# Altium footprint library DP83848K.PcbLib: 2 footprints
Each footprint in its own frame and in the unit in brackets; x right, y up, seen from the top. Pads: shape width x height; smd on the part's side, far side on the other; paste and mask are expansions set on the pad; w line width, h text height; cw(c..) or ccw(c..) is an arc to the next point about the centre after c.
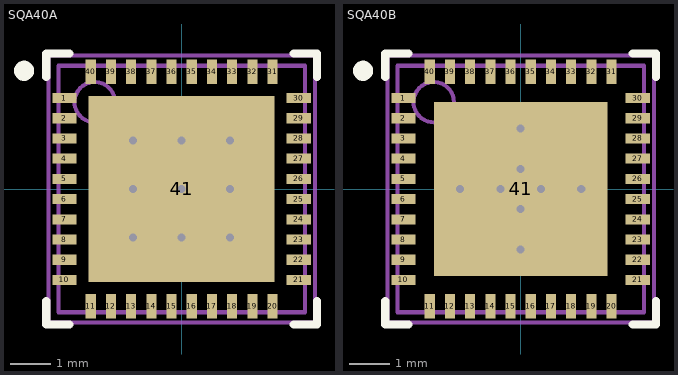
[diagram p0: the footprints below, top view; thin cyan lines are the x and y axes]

## SQA40A [mm] "QFN, 40-Leads, Body 6x6mm, Pitch 0.5mm, NSC Recommended"
height 0.8
pads (41):
  rect 0.6x0.25 smd paste-0.125 mask+0.051: 1(-2.9,2.25) 2(-2.9,1.75) 3(-2.9,1.25) 4(-2.9,0.75) 5(-2.9,0.25) 6(-2.9,-0.25) 7(-2.9,-0.75) 8(-2.9,-1.25) 9(-2.9,-1.75) 10(-2.9,-2.25) 21(2.9,-2.25) 22(2.9,-1.75) 23(2.9,-1.25) 24(2.9,-0.75) 25(2.9,-0.25) 26(2.9,0.25) 27(2.9,0.75) 28(2.9,1.25) 29(2.9,1.75) 30(2.9,2.25)
  rect 0.25x0.6 smd paste-0.125 mask+0.051: 11(-2.25,-2.9) 12(-1.75,-2.9) 13(-1.25,-2.9) 14(-0.75,-2.9) 15(-0.25,-2.9) 16(0.25,-2.9) 17(0.75,-2.9) 18(1.25,-2.9) 19(1.75,-2.9) 20(2.25,-2.9) 31(2.25,2.9) 32(1.75,2.9) 33(1.25,2.9) 34(0.75,2.9) 35(0.25,2.9) 36(-0.25,2.9) 37(-0.75,2.9) 38(-1.25,2.9) 39(-1.75,2.9) 40(-2.25,2.9)
  rect 4.6x4.6 smd paste-2.3 mask+0.051: 41(0,0)
via 1.2,0 diameter 0.5 hole 0.2
via -1.2,0 diameter 0.5 hole 0.2
via 0,0 diameter 0.5 hole 0.2
via 0,-1.2 diameter 0.5 hole 0.2
via -1.2,-1.2 diameter 0.5 hole 0.2
via 1.2,-1.2 diameter 0.5 hole 0.2
via 0,1.2 diameter 0.5 hole 0.2
via -1.2,1.2 diameter 0.5 hole 0.2
via 1.2,1.2 diameter 0.5 hole 0.2
Top Overlay:
  circle w0.25: c-3.9,2.925 r0.125
  lines w0.2: -3.35,-2.775 -3.35,-3.35 -2.775,-3.35 ; -3.35,2.775 -3.35,3.35 -2.775,3.35 ; 2.775,-3.35 3.35,-3.35 3.35,-2.775 ; 2.775,3.35 3.35,3.35 3.35,2.775
Top Paste:
  rectangle: 0.1,0.1 1.1,1.1
  rectangle: 1.3,1.3 2.3,2.3
  rectangle: 1.3,0.1 2.3,1.1
  rectangle: 0.1,1.3 1.1,2.3
  region: -0.1,2.3 -1.1,2.3 -1.1,1.3 -0.1,1.3
  region: -1.3,1.1 -2.3,1.1 -2.3,0.1 -1.3,0.1
  region: -1.3,2.3 -2.3,2.3 -2.3,1.3 -1.3,1.3
  region: -0.1,1.1 -1.1,1.1 -1.1,0.1 -0.1,0.1
  region: -0.1,-1.3 -1.1,-1.3 -1.1,-2.3 -0.1,-2.3
  region: -1.3,-0.1 -2.3,-0.1 -2.3,-1.1 -1.3,-1.1
  region: -1.3,-1.3 -2.3,-1.3 -2.3,-2.3 -1.3,-2.3
  region: -0.1,-0.1 -1.1,-0.1 -1.1,-1.1 -0.1,-1.1
  rectangle: 0.1,-2.3 1.1,-1.3
  rectangle: 1.3,-1.1 2.3,-0.1
  rectangle: 1.3,-2.3 2.3,-1.3
  rectangle: 0.1,-1.1 1.1,-0.1
  rectangle: -3.4,2.125 -2.7,2.375
  rectangle: -3.4,1.625 -2.7,1.875
  rectangle: -3.4,1.125 -2.7,1.375
  rectangle: -3.4,0.625 -2.7,0.875
  rectangle: -3.4,0.125 -2.7,0.375
  rectangle: -3.4,-0.375 -2.7,-0.125
  rectangle: -3.4,-0.875 -2.7,-0.625
  rectangle: -3.4,-1.375 -2.7,-1.125
  rectangle: -3.4,-1.875 -2.7,-1.625
  rectangle: -3.4,-2.375 -2.7,-2.125
  region: 2.375,-3.4 2.375,-2.7 2.125,-2.7 2.125,-3.4
  region: 1.875,-3.4 1.875,-2.7 1.625,-2.7 1.625,-3.4
  region: 1.375,-3.4 1.375,-2.7 1.125,-2.7 1.125,-3.4
  region: 0.875,-3.4 0.875,-2.7 0.625,-2.7 0.625,-3.4
  region: 0.375,-3.4 0.375,-2.7 0.125,-2.7 0.125,-3.4
  region: -0.125,-3.4 -0.125,-2.7 -0.375,-2.7 -0.375,-3.4
  region: -0.625,-3.4 -0.625,-2.7 -0.875,-2.7 -0.875,-3.4
  region: -1.125,-3.4 -1.125,-2.7 -1.375,-2.7 -1.375,-3.4
  region: -1.625,-3.4 -1.625,-2.7 -1.875,-2.7 -1.875,-3.4
  region: -2.125,-3.4 -2.125,-2.7 -2.375,-2.7 -2.375,-3.4
  region: 3.4,2.375 2.7,2.375 2.7,2.125 3.4,2.125
  region: 3.4,1.875 2.7,1.875 2.7,1.625 3.4,1.625
  region: 3.4,1.375 2.7,1.375 2.7,1.125 3.4,1.125
  region: 3.4,0.875 2.7,0.875 2.7,0.625 3.4,0.625
  region: 3.4,0.375 2.7,0.375 2.7,0.125 3.4,0.125
  region: 3.4,-0.125 2.7,-0.125 2.7,-0.375 3.4,-0.375
  region: 3.4,-0.625 2.7,-0.625 2.7,-0.875 3.4,-0.875
  region: 3.4,-1.125 2.7,-1.125 2.7,-1.375 3.4,-1.375
  region: 3.4,-1.625 2.7,-1.625 2.7,-1.875 3.4,-1.875
  region: 3.4,-2.125 2.7,-2.125 2.7,-2.375 3.4,-2.375
  region: -2.375,3.4 -2.375,2.7 -2.125,2.7 -2.125,3.4
  region: -1.875,3.4 -1.875,2.7 -1.625,2.7 -1.625,3.4
  region: -1.375,3.4 -1.375,2.7 -1.125,2.7 -1.125,3.4
  region: -0.875,3.4 -0.875,2.7 -0.625,2.7 -0.625,3.4
  region: -0.375,3.4 -0.375,2.7 -0.125,2.7 -0.125,3.4
  region: 0.125,3.4 0.125,2.7 0.375,2.7 0.375,3.4
  region: 0.625,3.4 0.625,2.7 0.875,2.7 0.875,3.4
  region: 1.125,3.4 1.125,2.7 1.375,2.7 1.375,3.4
  region: 1.625,3.4 1.625,2.7 1.875,2.7 1.875,3.4
  region: 2.125,3.4 2.125,2.7 2.375,2.7 2.375,3.4
M5 Assembly Top:
  text ".Designator" at -1.524,-0.508 h1.02
M13 Component Bodies Top:
  circle w0.1: c-2.15,2.15 r0.5
  lines w0.1: -3.05,-3.05 3.05,-3.05 3.05,3.05 -3.05,3.05 -3.05,-3.05
M15  Courtyards Top:
  lines w0.1: -0.5,0 0.5,0 ; 0,-0.5 0,0.5 ; -3.3,-3.3 3.3,-3.3 3.3,3.3 -3.3,3.3 -3.3,-3.3
3D body: height 0.8, standoff 0, extent -3.05,-3.05 3.05,3.05

## SQA40B [mm] "QFN, 40-Leads, Body 6x6mm, Pitch 0.5mm, NSC Recommended"
height 0.8
pads (41):
  rect 0.6x0.25 smd paste-0.125 mask+0.051: 1(-2.9,2.25) 2(-2.9,1.75) 3(-2.9,1.25) 4(-2.9,0.75) 5(-2.9,0.25) 6(-2.9,-0.25) 7(-2.9,-0.75) 8(-2.9,-1.25) 9(-2.9,-1.75) 10(-2.9,-2.25) 21(2.9,-2.25) 22(2.9,-1.75) 23(2.9,-1.25) 24(2.9,-0.75) 25(2.9,-0.25) 26(2.9,0.25) 27(2.9,0.75) 28(2.9,1.25) 29(2.9,1.75) 30(2.9,2.25)
  rect 0.25x0.6 smd paste-0.125 mask+0.051: 11(-2.25,-2.9) 12(-1.75,-2.9) 13(-1.25,-2.9) 14(-0.75,-2.9) 15(-0.25,-2.9) 16(0.25,-2.9) 17(0.75,-2.9) 18(1.25,-2.9) 19(1.75,-2.9) 20(2.25,-2.9) 31(2.25,2.9) 32(1.75,2.9) 33(1.25,2.9) 34(0.75,2.9) 35(0.25,2.9) 36(-0.25,2.9) 37(-0.75,2.9) 38(-1.25,2.9) 39(-1.75,2.9) 40(-2.25,2.9)
  rect 4.3x4.3 smd paste-2.15 mask+0.051: 41(0,0)
via -1.5,0 diameter 0.5 hole 0.2
via 0,-1.5 diameter 0.5 hole 0.2
via 0,1.5 diameter 0.5 hole 0.2
via 1.5,0 diameter 0.5 hole 0.2
via -0.5,0 diameter 0.5 hole 0.2
via 0.5,0 diameter 0.5 hole 0.2
via 0,-0.5 diameter 0.5 hole 0.2
via 0,0.5 diameter 0.5 hole 0.2
Top Overlay:
  circle w0.25: c-3.9,2.925 r0.125
  lines w0.2: -3.35,-2.775 -3.35,-3.35 -2.775,-3.35 ; -3.35,2.775 -3.35,3.35 -2.775,3.35 ; 2.775,-3.35 3.35,-3.35 3.35,-2.775 ; 2.775,3.35 3.35,3.35 3.35,2.775
Top Paste:
  rectangle: -3.4,2.125 -2.7,2.375
  rectangle: -3.4,1.625 -2.7,1.875
  rectangle: -3.4,1.125 -2.7,1.375
  rectangle: -3.4,0.625 -2.7,0.875
  rectangle: -3.4,0.125 -2.7,0.375
  rectangle: -3.4,-0.375 -2.7,-0.125
  rectangle: -3.4,-0.875 -2.7,-0.625
  rectangle: -3.4,-1.375 -2.7,-1.125
  rectangle: -3.4,-1.875 -2.7,-1.625
  rectangle: -3.4,-2.375 -2.7,-2.125
  region: 2.375,-3.4 2.375,-2.7 2.125,-2.7 2.125,-3.4
  region: 1.875,-3.4 1.875,-2.7 1.625,-2.7 1.625,-3.4
  region: 1.375,-3.4 1.375,-2.7 1.125,-2.7 1.125,-3.4
  region: 0.875,-3.4 0.875,-2.7 0.625,-2.7 0.625,-3.4
  region: 0.375,-3.4 0.375,-2.7 0.125,-2.7 0.125,-3.4
  region: -0.125,-3.4 -0.125,-2.7 -0.375,-2.7 -0.375,-3.4
  region: -0.625,-3.4 -0.625,-2.7 -0.875,-2.7 -0.875,-3.4
  region: -1.125,-3.4 -1.125,-2.7 -1.375,-2.7 -1.375,-3.4
  region: -1.625,-3.4 -1.625,-2.7 -1.875,-2.7 -1.875,-3.4
  region: -2.125,-3.4 -2.125,-2.7 -2.375,-2.7 -2.375,-3.4
  region: 3.4,2.375 2.7,2.375 2.7,2.125 3.4,2.125
  region: 3.4,1.875 2.7,1.875 2.7,1.625 3.4,1.625
  region: 3.4,1.375 2.7,1.375 2.7,1.125 3.4,1.125
  region: 3.4,0.875 2.7,0.875 2.7,0.625 3.4,0.625
  region: 3.4,0.375 2.7,0.375 2.7,0.125 3.4,0.125
  region: 3.4,-0.125 2.7,-0.125 2.7,-0.375 3.4,-0.375
  region: 3.4,-0.625 2.7,-0.625 2.7,-0.875 3.4,-0.875
  region: 3.4,-1.125 2.7,-1.125 2.7,-1.375 3.4,-1.375
  region: 3.4,-1.625 2.7,-1.625 2.7,-1.875 3.4,-1.875
  region: 3.4,-2.125 2.7,-2.125 2.7,-2.375 3.4,-2.375
  region: -2.375,3.4 -2.375,2.7 -2.125,2.7 -2.125,3.4
  region: -1.875,3.4 -1.875,2.7 -1.625,2.7 -1.625,3.4
  region: -1.375,3.4 -1.375,2.7 -1.125,2.7 -1.125,3.4
  region: -0.875,3.4 -0.875,2.7 -0.625,2.7 -0.625,3.4
  region: -0.375,3.4 -0.375,2.7 -0.125,2.7 -0.125,3.4
  region: 0.125,3.4 0.125,2.7 0.375,2.7 0.375,3.4
  region: 0.625,3.4 0.625,2.7 0.875,2.7 0.875,3.4
  region: 1.125,3.4 1.125,2.7 1.375,2.7 1.375,3.4
  region: 1.625,3.4 1.625,2.7 1.875,2.7 1.875,3.4
  region: 2.125,3.4 2.125,2.7 2.375,2.7 2.375,3.4
  rectangle: 0.1,0.1 2,2
  region: -0.1,2 -2,2 -2,0.1 -0.1,0.1
  region: -0.1,-0.1 -2,-0.1 -2,-2 -0.1,-2
  rectangle: 0.1,-2 2,-0.1
M5 Assembly Top:
  text ".Designator" at -1.524,-0.508 h1.02
M13 Component Bodies Top:
  circle w0.1: c-2.15,2.15 r0.5
  lines w0.1: -3.05,-3.05 -3.05,3.05 3.05,3.05 3.05,-3.05 -3.05,-3.05
M15  Courtyards Top:
  lines w0.1: -0.5,0 0.5,0 ; 0,-0.5 0,0.5 ; -3.3,-3.3 -3.3,3.3 3.3,3.3 3.3,-3.3 -3.3,-3.3
3D body: height 0.8, standoff 0, extent -3.05,-3.05 3.05,3.05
